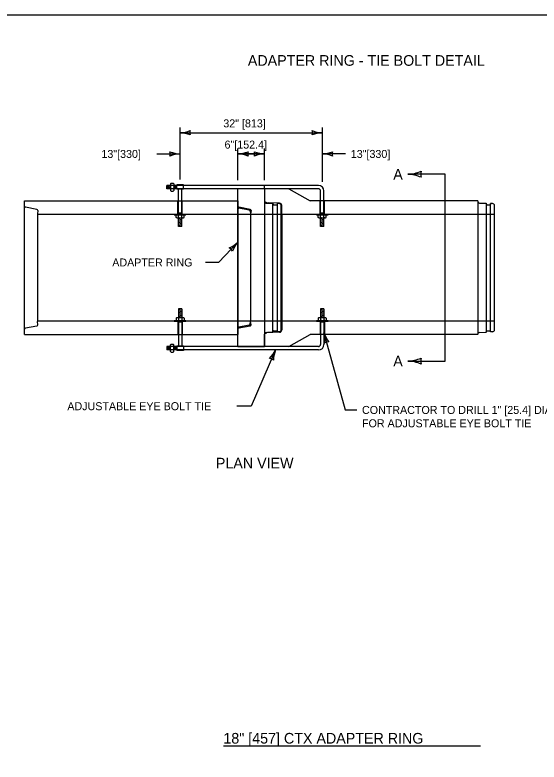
# Model space of a CAD drawing. Extents: x 49991.4 to 50021, y 49987.6 to 50011.4.
# Drawn here: x 50001.3 to 50005.23, y 49993.4 to 49999 of the extents above; entities that cross this region are included whole.
import ezdxf

# ---------------------------------------------------------------- set-up
doc = ezdxf.new("R2010")
doc.units = 0
for name, color, linetype in [('CONCRETE', 7, 'Continuous'), ('DASH', 7, 'Continuous'), ('Default', 7, 'Continuous'), ('Level 1', 7, 'Continuous'), ('Level 2', 7, 'Continuous'), ('Level 3', 7, 'Continuous'), ('Level 4', 7, 'Continuous'), ('Level 6', 7, 'Continuous'), ('TEXT', 7, 'Continuous')]:
    doc.layers.add(name, color=color, linetype=linetype)

msp = doc.modelspace()

# ---------------------------------------------------------------- linework, layer by layer
at = {"layer": 'CONCRETE'}
for p, q in [((50003.1721, 49997.6963), (50002.9721, 49997.6963)), ((50003.1721, 49997.6963), (50003.1721, 49996.513)), ((50003.3554, 49997.6963), (50003.1721, 49997.6963)), ((50002.9721, 49997.6046), (50002.9721, 49997.5656)), ((50002.9721, 49997.6046), (50002.9721, 49996.6046)), ((50004.7721, 49997.6046), (50004.7721, 49997.6017)), ((50002.9721, 49996.6046), (50002.9721, 49996.6436)), ((50004.7721, 49996.6046), (50004.7721, 49996.6076)), ((50002.9721, 49996.513), (50003.1721, 49996.513)), ((50003.3554, 49996.513), (50003.1721, 49996.513))]:
    msp.add_line(p, q, dxfattribs=at)
at = {"layer": 'DASH'}
for p, q in [((50003.1721, 49997.6046), (50003.1721, 49997.6017)), ((50003.1721, 49996.6046), (50003.1721, 49996.6076))]:
    msp.add_line(p, q, dxfattribs=at)
at = {"layer": 'Default'}
for p, q in [((50002.9721, 49997.6046), (50002.9721, 49997.5589)), ((50002.9721, 49996.6046), (50002.9721, 49996.6503))]:
    msp.add_line(p, q, dxfattribs=at)
at = {"layer": 'Level 1'}
for p, q in [((50002.4675, 49997.7213), (50002.4387, 49997.7213)), ((50002.4387, 49997.6963), (50002.4387, 49997.7213)), ((50002.4423, 49997.6963), (50002.4387, 49997.7118)), ((50002.4675, 49997.6963), (50002.4387, 49997.6963)), ((50002.4523, 49997.6963), (50002.4465, 49997.7213)), ((50002.4623, 49997.6963), (50002.4565, 49997.7213)), ((50002.4675, 49997.7171), (50002.4665, 49997.7213)), ((50002.4675, 49997.7336), (50002.4717, 49997.7388)), ((50002.4675, 49997.7336), (50002.4675, 49997.6839)), ((50002.4675, 49997.7264), (50002.4717, 49997.7213)), ((50002.4675, 49997.7161), (50002.4717, 49997.7213)), ((50002.4675, 49997.7014), (50002.4717, 49997.6963)), ((50002.4675, 49997.6911), (50002.4717, 49997.6963)), ((50002.4717, 49997.7388), (50002.4866, 49997.7388)), ((50002.4866, 49997.7213), (50002.4717, 49997.7213)), ((50002.4866, 49997.6963), (50002.4717, 49997.6963)), ((50002.4908, 49997.7336), (50002.4866, 49997.7388)), ((50002.4908, 49997.7264), (50002.4866, 49997.7213)), ((50002.4908, 49997.7161), (50002.4866, 49997.7213)), ((50002.4908, 49997.7014), (50002.4866, 49997.6963)), ((50002.4908, 49997.6911), (50002.4866, 49997.6963)), ((50002.4908, 49997.7336), (50002.4908, 49997.6839)), ((50003.5762, 49997.7213), (50002.4908, 49997.7213)), ((50002.4923, 49997.6963), (50002.4908, 49997.7028)), ((50003.5762, 49997.6963), (50002.4908, 49997.6963)), ((50002.5023, 49997.6963), (50002.4965, 49997.7213)), ((50002.5123, 49997.6963), (50002.5065, 49997.7213)), ((50002.5137, 49997.6921), (50002.5137, 49997.7254)), ((50002.5637, 49997.7254), (50002.5137, 49997.7254)), ((50002.5637, 49997.6921), (50002.5137, 49997.6921)), ((50002.5262, 49997.5046), (50002.5262, 49997.6921)), ((50002.5512, 49997.5046), (50002.5512, 49997.6921)), ((50002.5637, 49997.6921), (50002.5637, 49997.7254)), ((50002.9721, 49996.513), (50002.9721, 49997.6963)), ((50003.1721, 49997.6963), (50003.1721, 49997.7213)), ((50003.1721, 49997.6963), (50003.1721, 49997.6075)), ((50003.3554, 49997.6963), (50003.5141, 49997.6046)), ((50002.4675, 49997.6839), (50002.4717, 49997.6787)), ((50002.4717, 49997.6787), (50002.4866, 49997.6787)), ((50002.4908, 49997.6839), (50002.4866, 49997.6787)), ((50003.5929, 49997.5046), (50003.5929, 49997.6796)), ((50003.6179, 49997.5046), (50003.6179, 49997.6796)), ((50001.3721, 49997.6046), (50002.9721, 49997.6046)), ((50002.9721, 49996.6046), (50002.9721, 49997.6046)), ((50003.1721, 49997.6075), (50003.1721, 49996.6018)), ((50004.7721, 49997.6046), (50003.5141, 49997.6046)), ((50004.7721, 49997.6031), (50004.7721, 49996.6061)), ((50004.7842, 49997.5892), (50004.8344, 49997.5876)), ((50004.8344, 49997.5876), (50004.8344, 49996.6217)), ((50004.8344, 49997.5876), (50004.8359, 49997.5792)), ((50004.8677, 49997.5856), (50004.8666, 49997.5792)), ((50004.8677, 49996.6237), (50004.8677, 49997.5856)), ((50004.8809, 49997.5851), (50004.8677, 49997.5856)), ((50004.8389, 49997.5766), (50004.8635, 49997.5766)), ((50004.8971, 49996.6407), (50004.8971, 49997.5685)), ((50002.4947, 49997.5011), (50002.4947, 49997.5046)), ((50002.4947, 49997.5046), (50002.5827, 49997.5046)), ((50002.4947, 49997.5011), (50002.5827, 49997.5011)), ((50002.5138, 49997.5011), (50002.5087, 49997.4968)), ((50002.5087, 49997.482), (50002.5087, 49997.4968)), ((50002.5138, 49997.4777), (50002.5087, 49997.482)), ((50002.5138, 49997.5011), (50002.5636, 49997.5011)), ((50002.5138, 49997.4777), (50002.5636, 49997.4777)), ((50002.521, 49997.5011), (50002.5262, 49997.4968)), ((50002.521, 49997.4777), (50002.5262, 49997.482)), ((50002.5512, 49997.5129), (50002.5262, 49997.5129)), ((50002.5356, 49997.5129), (50002.5262, 49997.5108)), ((50002.5314, 49997.5011), (50002.5262, 49997.4968)), ((50002.5262, 49997.482), (50002.5262, 49997.4968)), ((50002.5262, 49997.4842), (50002.5262, 49997.4968)), ((50002.5314, 49997.4777), (50002.5262, 49997.482)), ((50002.5262, 49997.4129), (50002.5262, 49997.4777)), ((50002.5512, 49997.4765), (50002.5262, 49997.4707)), ((50002.5512, 49997.4665), (50002.5262, 49997.4607)), ((50002.5512, 49997.5065), (50002.5429, 49997.5046)), ((50002.546, 49997.5011), (50002.5512, 49997.4968)), ((50002.546, 49997.4777), (50002.5512, 49997.482)), ((50002.5564, 49997.5011), (50002.5512, 49997.4968)), ((50002.5512, 49997.482), (50002.5512, 49997.4968)), ((50002.5512, 49997.4842), (50002.5512, 49997.4968)), ((50002.5564, 49997.4777), (50002.5512, 49997.482)), ((50002.5512, 49997.4129), (50002.5512, 49997.4777)), ((50002.5636, 49997.5011), (50002.5688, 49997.4968)), ((50002.5636, 49997.4777), (50002.5688, 49997.482)), ((50002.5688, 49997.482), (50002.5688, 49997.4968)), ((50002.5827, 49997.5011), (50002.5827, 49997.5046)), ((50003.5614, 49997.5011), (50003.5614, 49997.5046)), ((50003.5614, 49997.5046), (50003.6494, 49997.5046)), ((50003.5614, 49997.5011), (50003.6494, 49997.5011)), ((50003.5805, 49997.5011), (50003.5753, 49997.4968)), ((50003.5753, 49997.482), (50003.5753, 49997.4968)), ((50003.5805, 49997.4777), (50003.5753, 49997.482)), ((50003.5805, 49997.5011), (50003.6303, 49997.5011)), ((50003.5805, 49997.4777), (50003.6303, 49997.4777)), ((50003.5877, 49997.5011), (50003.5929, 49997.4968)), ((50003.5877, 49997.4777), (50003.5929, 49997.482)), ((50003.6179, 49997.5129), (50003.5929, 49997.5129)), ((50003.6023, 49997.5129), (50003.5929, 49997.5108)), ((50003.5981, 49997.5011), (50003.5929, 49997.4968)), ((50003.5929, 49997.482), (50003.5929, 49997.4968)), ((50003.5929, 49997.4842), (50003.5929, 49997.4968)), ((50003.5981, 49997.4777), (50003.5929, 49997.482)), ((50003.5929, 49997.4129), (50003.5929, 49997.4777)), ((50003.6179, 49997.4765), (50003.5929, 49997.4707)), ((50003.6179, 49997.4665), (50003.5929, 49997.4607)), ((50003.6179, 49997.5065), (50003.6096, 49997.5046)), ((50003.6127, 49997.5011), (50003.6179, 49997.4968)), ((50003.6127, 49997.4777), (50003.6179, 49997.482)), ((50003.6231, 49997.5011), (50003.6179, 49997.4968)), ((50003.6179, 49997.482), (50003.6179, 49997.4968)), ((50003.6179, 49997.4842), (50003.6179, 49997.4968)), ((50003.6231, 49997.4777), (50003.6179, 49997.482)), ((50003.6179, 49997.4129), (50003.6179, 49997.4777)), ((50003.6303, 49997.5011), (50003.6355, 49997.4968)), ((50003.6303, 49997.4777), (50003.6355, 49997.482)), ((50003.6355, 49997.482), (50003.6355, 49997.4968)), ((50003.6494, 49997.5011), (50003.6494, 49997.5046)), ((50002.5512, 49997.4565), (50002.5262, 49997.4507)), ((50002.5512, 49997.4465), (50002.5262, 49997.4407)), ((50002.5512, 49997.4365), (50002.5262, 49997.4307)), ((50002.5512, 49997.4265), (50002.5262, 49997.4207)), ((50002.5512, 49997.4129), (50002.5262, 49997.4129)), ((50002.5512, 49997.4129), (50002.5262, 49997.4129)), ((50002.5512, 49997.4165), (50002.5357, 49997.4129)), ((50003.6179, 49997.4565), (50003.5929, 49997.4507)), ((50003.6179, 49997.4465), (50003.5929, 49997.4407)), ((50003.6179, 49997.4365), (50003.5929, 49997.4307)), ((50003.6179, 49997.4265), (50003.5929, 49997.4207)), ((50003.6179, 49997.4129), (50003.5929, 49997.4129)), ((50003.6179, 49997.4129), (50003.5929, 49997.4129)), ((50003.6179, 49997.4165), (50003.6024, 49997.4129)), ((50002.5262, 49996.7963), (50002.5262, 49996.7315)), ((50002.5512, 49996.7963), (50002.5262, 49996.7963)), ((50002.5512, 49996.7963), (50002.5262, 49996.7963)), ((50002.5512, 49996.7927), (50002.5357, 49996.7963)), ((50002.5512, 49996.7963), (50002.5512, 49996.7315)), ((50003.6179, 49996.7963), (50003.5929, 49996.7963)), ((50003.5929, 49996.7963), (50003.5929, 49996.7315)), ((50003.6179, 49996.7963), (50003.5929, 49996.7963)), ((50003.6179, 49996.7927), (50003.6024, 49996.7963)), ((50003.6179, 49996.7963), (50003.6179, 49996.7315)), ((50002.5512, 49996.7827), (50002.5262, 49996.7885)), ((50002.5512, 49996.7727), (50002.5262, 49996.7785)), ((50002.5512, 49996.7627), (50002.5262, 49996.7685)), ((50002.5512, 49996.7527), (50002.5262, 49996.7585)), ((50002.5512, 49996.7427), (50002.5262, 49996.7485)), ((50002.5512, 49996.7327), (50002.5262, 49996.7385)), ((50003.6179, 49996.7827), (50003.5929, 49996.7885)), ((50003.6179, 49996.7727), (50003.5929, 49996.7785)), ((50003.6179, 49996.7627), (50003.5929, 49996.7685)), ((50003.6179, 49996.7527), (50003.5929, 49996.7585)), ((50003.6179, 49996.7427), (50003.5929, 49996.7485)), ((50003.6179, 49996.7327), (50003.5929, 49996.7385)), ((50002.4947, 49996.7081), (50002.5827, 49996.7081)), ((50002.4947, 49996.7046), (50002.5827, 49996.7046)), ((50002.5138, 49996.7315), (50002.5087, 49996.7272)), ((50002.5087, 49996.7272), (50002.5087, 49996.7124)), ((50002.5138, 49996.7081), (50002.5087, 49996.7124)), ((50002.5138, 49996.7315), (50002.5636, 49996.7315)), ((50002.521, 49996.7315), (50002.5262, 49996.7272)), ((50002.521, 49996.7081), (50002.5262, 49996.7124)), ((50002.5314, 49996.7315), (50002.5262, 49996.7272)), ((50002.5262, 49996.7272), (50002.5262, 49996.7124)), ((50002.5262, 49996.725), (50002.5262, 49996.7124)), ((50002.5314, 49996.7081), (50002.5262, 49996.7124)), ((50002.5262, 49996.7046), (50002.5262, 49996.5171)), ((50002.5356, 49996.6963), (50002.5262, 49996.6985)), ((50002.5512, 49996.6963), (50002.5262, 49996.6963)), ((50002.5512, 49996.7027), (50002.5429, 49996.7046)), ((50002.546, 49996.7315), (50002.5512, 49996.7272)), ((50002.546, 49996.7081), (50002.5512, 49996.7124)), ((50002.5564, 49996.7315), (50002.5512, 49996.7272)), ((50002.5512, 49996.7272), (50002.5512, 49996.7124)), ((50002.5512, 49996.725), (50002.5512, 49996.7124)), ((50002.5564, 49996.7081), (50002.5512, 49996.7124)), ((50002.5512, 49996.7046), (50002.5512, 49996.5171)), ((50002.5636, 49996.7315), (50002.5688, 49996.7272)), ((50002.5636, 49996.7081), (50002.5688, 49996.7124)), ((50002.5688, 49996.7272), (50002.5688, 49996.7124)), ((50003.5614, 49996.7081), (50003.6494, 49996.7081)), ((50003.5614, 49996.7081), (50003.5614, 49996.7046)), ((50003.5614, 49996.7046), (50003.6494, 49996.7046)), ((50003.5805, 49996.7315), (50003.5753, 49996.7272)), ((50003.5753, 49996.7272), (50003.5753, 49996.7124)), ((50003.5805, 49996.7081), (50003.5753, 49996.7124)), ((50003.5805, 49996.7315), (50003.6303, 49996.7315)), ((50003.5877, 49996.7315), (50003.5929, 49996.7272)), ((50003.5877, 49996.7081), (50003.5929, 49996.7124)), ((50003.5981, 49996.7315), (50003.5929, 49996.7272)), ((50003.5929, 49996.7272), (50003.5929, 49996.7124)), ((50003.5929, 49996.725), (50003.5929, 49996.7124)), ((50003.5981, 49996.7081), (50003.5929, 49996.7124)), ((50003.5929, 49996.7046), (50003.5929, 49996.5296)), ((50003.6023, 49996.6963), (50003.5929, 49996.6985)), ((50003.6179, 49996.6963), (50003.5929, 49996.6963)), ((50003.6179, 49996.7027), (50003.6096, 49996.7046)), ((50003.6127, 49996.7315), (50003.6179, 49996.7272)), ((50003.6127, 49996.7081), (50003.6179, 49996.7124)), ((50003.6231, 49996.7315), (50003.6179, 49996.7272)), ((50003.6179, 49996.7272), (50003.6179, 49996.7124)), ((50003.6179, 49996.725), (50003.6179, 49996.7124)), ((50003.6231, 49996.7081), (50003.6179, 49996.7124)), ((50003.6179, 49996.7046), (50003.6179, 49996.5296)), ((50003.6303, 49996.7315), (50003.6355, 49996.7272)), ((50003.6303, 49996.7081), (50003.6355, 49996.7124)), ((50003.6355, 49996.7272), (50003.6355, 49996.7124)), ((50003.6494, 49996.7081), (50003.6494, 49996.7046)), ((50004.8344, 49996.6217), (50004.8359, 49996.63)), ((50004.8389, 49996.6326), (50004.8635, 49996.6326)), ((50004.8677, 49996.6237), (50004.8666, 49996.63)), ((50001.3721, 49996.6046), (50002.9721, 49996.6046)), ((50003.1721, 49996.513), (50003.1721, 49996.6018)), ((50003.3554, 49996.513), (50003.5141, 49996.6046)), ((50004.7721, 49996.6046), (50003.5141, 49996.6046)), ((50004.7842, 49996.62), (50004.8344, 49996.6217)), ((50004.8809, 49996.6241), (50004.8677, 49996.6237)), ((50002.4675, 49996.5253), (50002.4717, 49996.5305)), ((50002.4675, 49996.4756), (50002.4675, 49996.5253)), ((50002.4675, 49996.5181), (50002.4717, 49996.513)), ((50002.4717, 49996.5305), (50002.4866, 49996.5305)), ((50002.4908, 49996.5253), (50002.4866, 49996.5305)), ((50002.4908, 49996.5181), (50002.4866, 49996.513)), ((50002.4908, 49996.4756), (50002.4908, 49996.5253)), ((50002.5137, 49996.5171), (50002.5137, 49996.4838)), ((50002.5637, 49996.5171), (50002.5137, 49996.5171)), ((50002.5637, 49996.5171), (50002.5637, 49996.4838)), ((50002.4675, 49996.513), (50002.4387, 49996.513)), ((50002.4387, 49996.513), (50002.4387, 49996.488)), ((50002.4423, 49996.513), (50002.4387, 49996.4974)), ((50002.4675, 49996.488), (50002.4387, 49996.488)), ((50002.4523, 49996.513), (50002.4465, 49996.488)), ((50002.4623, 49996.513), (50002.4565, 49996.488)), ((50002.4675, 49996.4921), (50002.4665, 49996.488)), ((50002.4675, 49996.5078), (50002.4717, 49996.513)), ((50002.4675, 49996.4931), (50002.4717, 49996.488)), ((50002.4675, 49996.4828), (50002.4717, 49996.488)), ((50002.4675, 49996.4756), (50002.4717, 49996.4704)), ((50002.4866, 49996.513), (50002.4717, 49996.513)), ((50002.4866, 49996.488), (50002.4717, 49996.488)), ((50002.4717, 49996.4704), (50002.4866, 49996.4704)), ((50002.4908, 49996.5078), (50002.4866, 49996.513)), ((50002.4908, 49996.4931), (50002.4866, 49996.488)), ((50002.4908, 49996.4828), (50002.4866, 49996.488)), ((50002.4908, 49996.4756), (50002.4866, 49996.4704)), ((50003.5762, 49996.513), (50002.4908, 49996.513)), ((50002.4923, 49996.513), (50002.4908, 49996.5065)), ((50003.5762, 49996.488), (50002.4908, 49996.488)), ((50002.5023, 49996.513), (50002.4965, 49996.488)), ((50002.5123, 49996.513), (50002.5065, 49996.488)), ((50002.5637, 49996.4838), (50002.5137, 49996.4838))]:
    msp.add_line(p, q, dxfattribs=at)
msp.add_lwpolyline([(49999.3835, 49998.9992), (50016.7501, 49998.9992), (50016.7501, 49987.7988), (49999.3835, 49987.7988)], close=True, dxfattribs=at)
for centre, radius, start, end in [((50003.5762, 49997.6796), 0.0417, 0, 90), ((50003.5762, 49997.6796), 0.0167, 0, 90), ((50004.7846, 49997.6017), 0.0125, 180, 268.167), ((50004.8389, 49997.5798), 0.00313, 190, 270), ((50004.8635, 49997.5798), 0.00313, 270, 350), ((50004.8804, 49997.5685), 0.0167, 0, 88.167), ((50004.8389, 49996.6294), 0.00313, 90, 170), ((50004.8635, 49996.6294), 0.00313, 10, 90), ((50004.8804, 49996.6407), 0.0167, 271.833, 0), ((50004.7846, 49996.6076), 0.0125, 91.833, 180), ((50003.5762, 49996.5296), 0.0167, 270, 0), ((50003.5762, 49996.5296), 0.0417, 270, 0)]:
    msp.add_arc(centre, radius, start, end, dxfattribs=at)
at = {"layer": 'Level 2'}
msp.add_line((50002.8633, 49993.5213), (50004.7921, 49993.5213), dxfattribs=at)
at = {"layer": 'Level 3'}
for p, q in [((50002.5387, 49997.7654), (50002.5387, 49998.1564)), ((50003.6057, 49997.7491), (50003.6057, 49998.1564)), ((50002.5387, 49998.1164), (50003.6057, 49998.1164)), ((50002.5387, 49997.7654), (50002.5387, 49997.9973)), ((50002.9723, 49997.7613), (50002.9723, 49997.9973)), ((50003.1721, 49997.7613), (50003.1721, 49997.9973)), ((50003.6057, 49997.7613), (50003.6057, 49997.9973)), ((50002.3653, 49997.9573), (50002.5387, 49997.9573)), ((50003.1721, 49997.9573), (50002.9723, 49997.9573)), ((50002.9723, 49997.9573), (50003.1721, 49997.9573)), ((50003.7791, 49997.9573), (50003.6057, 49997.9573))]:
    msp.add_line(p, q, dxfattribs=at)
for points in [[(50002.9721, 49997.2957), (50002.827, 49997.1446), (50002.7283, 49997.1446)], [(50003.6179, 49996.6171), (50003.777, 49996.0383), (50003.8633, 49996.0383)], [(50003.2542, 49996.488), (50003.0705, 49996.0663), (50002.963, 49996.0663)]]:
    msp.add_lwpolyline(points, dxfattribs=at)
for centre, radius, start, end in [((50002.5273, 49998.3491), 0.233, 272.8102, 292.0601), ((50002.5295, 49997.8943), 0.2223, 67.4389, 87.6225), ((50002.6669, 49998.1164), 0.0548, 162.1218, 197.8441), ((50003.6149, 49998.3385), 0.2223, 247.4389, 267.6225), ((50003.4775, 49998.1164), 0.0548, 342.1218, 17.8441), ((50003.6171, 49997.8837), 0.233, 92.8102, 112.0601), ((50002.5479, 49998.1794), 0.2223, 247.4389, 267.6225), ((50002.4105, 49997.9573), 0.0548, 342.1218, 17.8441), ((50002.9609, 49998.19), 0.233, 272.8102, 292.0601), ((50003.1005, 49997.9573), 0.0548, 162.1218, 197.8441), ((50003.1813, 49998.1794), 0.2223, 247.4389, 267.6225), ((50003.0438, 49997.9573), 0.0548, 342.1218, 17.8441), ((50003.5943, 49998.19), 0.233, 272.8102, 292.0601), ((50003.7339, 49997.9573), 0.0548, 162.1218, 197.8441), ((50002.5501, 49997.7246), 0.233, 92.8102, 112.0601), ((50002.9631, 49997.7352), 0.2223, 67.4389, 87.6225), ((50003.1835, 49997.7246), 0.233, 92.8102, 112.0601), ((50003.5965, 49997.7352), 0.2223, 67.4389, 87.6225), ((50004.231, 49998.1149), 0.3107, 272.8102, 292.0601), ((50004.234, 49997.5084), 0.2964, 67.4389, 87.6225), ((50004.4172, 49997.8046), 0.073, 162.1218, 197.8441), ((50002.8182, 49997.4562), 0.2223, 293.603, 313.7865), ((50002.8832, 49997.2032), 0.0548, 28.2858, 64.0082), ((50003.1478, 49997.1427), 0.233, 138.9743, 158.2242), ((50003.4013, 49996.5671), 0.2223, 352.809, 12.9925), ((50003.8393, 49996.6898), 0.233, 198.1803, 217.4302), ((50003.6518, 49996.4935), 0.0548, 87.4918, 123.2142), ((50003.0542, 49996.5851), 0.2223, 313.9109, 334.0944), ((50003.4721, 49996.4055), 0.233, 159.2822, 178.5321), ((50003.203, 49996.3704), 0.0548, 48.5937, 84.3161), ((50004.231, 49996.7149), 0.3107, 272.8102, 292.0601), ((50004.234, 49996.1084), 0.2964, 67.4389, 87.6225), ((50004.4172, 49996.4046), 0.073, 162.1218, 197.8441)]:
    msp.add_arc(centre, radius, start, end, dxfattribs=at)
at = {"layer": 'Level 4'}
for p, q in [((50001.3721, 49996.6046), (50001.3721, 49997.6046)), ((50002.5221, 49997.5046), (50002.5221, 49997.6046)), ((50002.5554, 49997.5046), (50002.5554, 49997.6046)), ((50003.1842, 49997.5892), (50003.2344, 49997.5876)), ((50003.2851, 49997.588), (50003.2012, 49997.5907)), ((50003.2344, 49996.6217), (50003.2344, 49997.5876)), ((50003.2344, 49997.5876), (50003.2359, 49997.5792)), ((50003.2677, 49997.5856), (50003.2666, 49997.5792)), ((50003.2677, 49997.5856), (50003.2677, 49996.6237)), ((50003.2809, 49997.5851), (50003.2677, 49997.5856)), ((50003.5887, 49997.5046), (50003.5887, 49997.6046)), ((50003.6221, 49997.5046), (50003.6221, 49997.6046)), ((50001.4643, 49997.5419), (50001.3789, 49997.5574)), ((50001.4711, 49997.5327), (50001.4679, 49997.5072)), ((50003.0643, 49997.5419), (50002.9789, 49997.5574)), ((50003.0579, 49997.5364), (50002.9789, 49997.5507)), ((50003.0646, 49997.5295), (50003.0679, 49997.5088)), ((50003.0711, 49997.5327), (50003.0679, 49997.5072)), ((50003.2389, 49997.5766), (50003.2635, 49997.5766)), ((50003.2971, 49996.6407), (50003.2971, 49997.5685)), ((50003.3012, 49997.5046), (50003.3012, 49997.5714)), ((50001.4679, 49997.5072), (50001.4679, 49996.702)), ((50004.8971, 49997.5046), (50001.4679, 49997.5046)), ((50003.0679, 49997.5088), (50003.0679, 49997.5046)), ((50003.0679, 49997.5046), (50003.0679, 49996.7025)), ((50003.3012, 49997.5046), (50003.3012, 49996.7046)), ((50004.8971, 49996.7046), (50001.4679, 49996.7046)), ((50001.4711, 49996.6765), (50001.4679, 49996.702)), ((50002.5221, 49996.7046), (50002.5221, 49996.6046)), ((50002.5554, 49996.7046), (50002.5554, 49996.6046)), ((50003.0646, 49996.6797), (50003.0679, 49996.7004)), ((50003.0679, 49996.7004), (50003.0679, 49996.7046)), ((50003.0711, 49996.6765), (50003.0679, 49996.702)), ((50003.3012, 49996.7046), (50003.3012, 49996.6378)), ((50003.5887, 49996.7046), (50003.5887, 49996.6046)), ((50003.6221, 49996.7046), (50003.6221, 49996.6046)), ((50001.3721, 49996.6046), (50001.3721, 49996.6436)), ((50001.4643, 49996.6673), (50001.3789, 49996.6518)), ((50003.0579, 49996.6728), (50002.9789, 49996.6585)), ((50003.0643, 49996.6673), (50002.9789, 49996.6518)), ((50003.2344, 49996.6217), (50003.2359, 49996.63)), ((50003.2389, 49996.6326), (50003.2635, 49996.6326)), ((50003.2677, 49996.6237), (50003.2666, 49996.63)), ((50003.1842, 49996.62), (50003.2344, 49996.6217)), ((50003.2851, 49996.6212), (50003.2012, 49996.6185)), ((50003.2809, 49996.6241), (50003.2677, 49996.6237))]:
    msp.add_line(p, q, dxfattribs=at)
for centre, radius, start, end in [((50003.1804, 49997.6075), 0.00833, 180, 228.319), ((50003.1846, 49997.6017), 0.0125, 180, 268.167), ((50003.2026, 49997.6324), 0.0417, 228.319, 268.167), ((50003.2389, 49997.5798), 0.00313, 190, 270), ((50003.2635, 49997.5798), 0.00313, 270, 350), ((50003.2804, 49997.5685), 0.0167, 0, 88.167), ((50003.2846, 49997.5714), 0.0167, 0, 88.167), ((50001.3804, 49997.5656), 0.00833, 180, 259.7498), ((50001.4628, 49997.5337), 0.00833, 352.875, 79.7498), ((50002.9804, 49997.5656), 0.00833, 180, 259.7498), ((50002.9804, 49997.5589), 0.00833, 180, 259.7456), ((50003.0564, 49997.5282), 0.00833, 8.9081, 79.7456), ((50003.0628, 49997.5337), 0.00833, 352.875, 79.7498), ((50001.3804, 49996.6436), 0.00833, 100.2502, 180), ((50001.4628, 49996.6755), 0.00833, 280.2502, 7.125), ((50002.9804, 49996.6503), 0.00833, 100.2544, 180), ((50002.9804, 49996.6436), 0.00833, 100.2502, 180), ((50003.0564, 49996.681), 0.00833, 280.2544, 351.0919), ((50003.0628, 49996.6755), 0.00833, 280.2502, 7.125), ((50003.2389, 49996.6294), 0.00313, 90, 170), ((50003.2635, 49996.6294), 0.00313, 10, 90), ((50003.2804, 49996.6407), 0.0167, 271.833, 0), ((50003.2846, 49996.6378), 0.0167, 271.833, 0), ((50003.1846, 49996.6076), 0.0125, 91.833, 180), ((50003.1804, 49996.6018), 0.00833, 131.681, 180), ((50003.2026, 49996.5769), 0.0417, 91.833, 131.681)]:
    msp.add_arc(centre, radius, start, end, dxfattribs=at)
at = {"layer": 'Level 6'}
msp.add_lwpolyline([(50004.2463, 49996.4046), (50004.5263, 49996.4046), (50004.5263, 49997.8046), (50004.2463, 49997.8046)], dxfattribs=at)
at = {"layer": 'TEXT'}
for p, q in [((50002.4947, 49996.7081), (50002.4947, 49996.7046)), ((50002.5138, 49996.7081), (50002.5636, 49996.7081)), ((50002.5827, 49996.7081), (50002.5827, 49996.7046)), ((50003.5805, 49996.7081), (50003.6303, 49996.7081))]:
    msp.add_line(p, q, dxfattribs=at)

# ---------------------------------------------------------------- texts
at = {"layer": 'Level 2'}
for s, height, p in [('ADAPTER RING - TIE BOLT DETAIL', 0.08, (50003.0468, 49998.6181)), ('32" [813]', 0.06, (50002.8628, 49998.1564)), ('6"[152.4]', 0.06, (50002.872, 49997.9973)), ('13"[330]', 0.06, (50001.9485, 49997.9273)), ('13"[330]', 0.06, (50003.8191, 49997.9273)), ('A', 0.08, (50004.1376, 49997.7646)), ('ADAPTER RING', 0.06, (50002.0298, 49997.1137)), ('A', 0.08, (50004.1376, 49996.3646)), ('ADJUSTABLE EYE BOLT TIE', 0.06, (50001.6929, 49996.0363)), ('CONTRACTOR TO DRILL 1" [25.4] DIA.HOLES', 0.06, (50003.9033, 49996.0083)), ('FOR ADJUSTABLE EYE BOLT TIE', 0.06, (50003.9033, 49995.9083)), ('PLAN VIEW', 0.08, (50002.807, 49995.5996)), ('18" [457] CTX ADAPTER RING', 0.08, (50002.8633, 49993.5373))]:
    msp.add_text(s, height=height, dxfattribs=at).set_placement(p)

doc.saveas('drawing.dxf')
